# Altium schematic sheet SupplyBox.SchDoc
size C; SheetNumber: 1; SheetTotal: 1
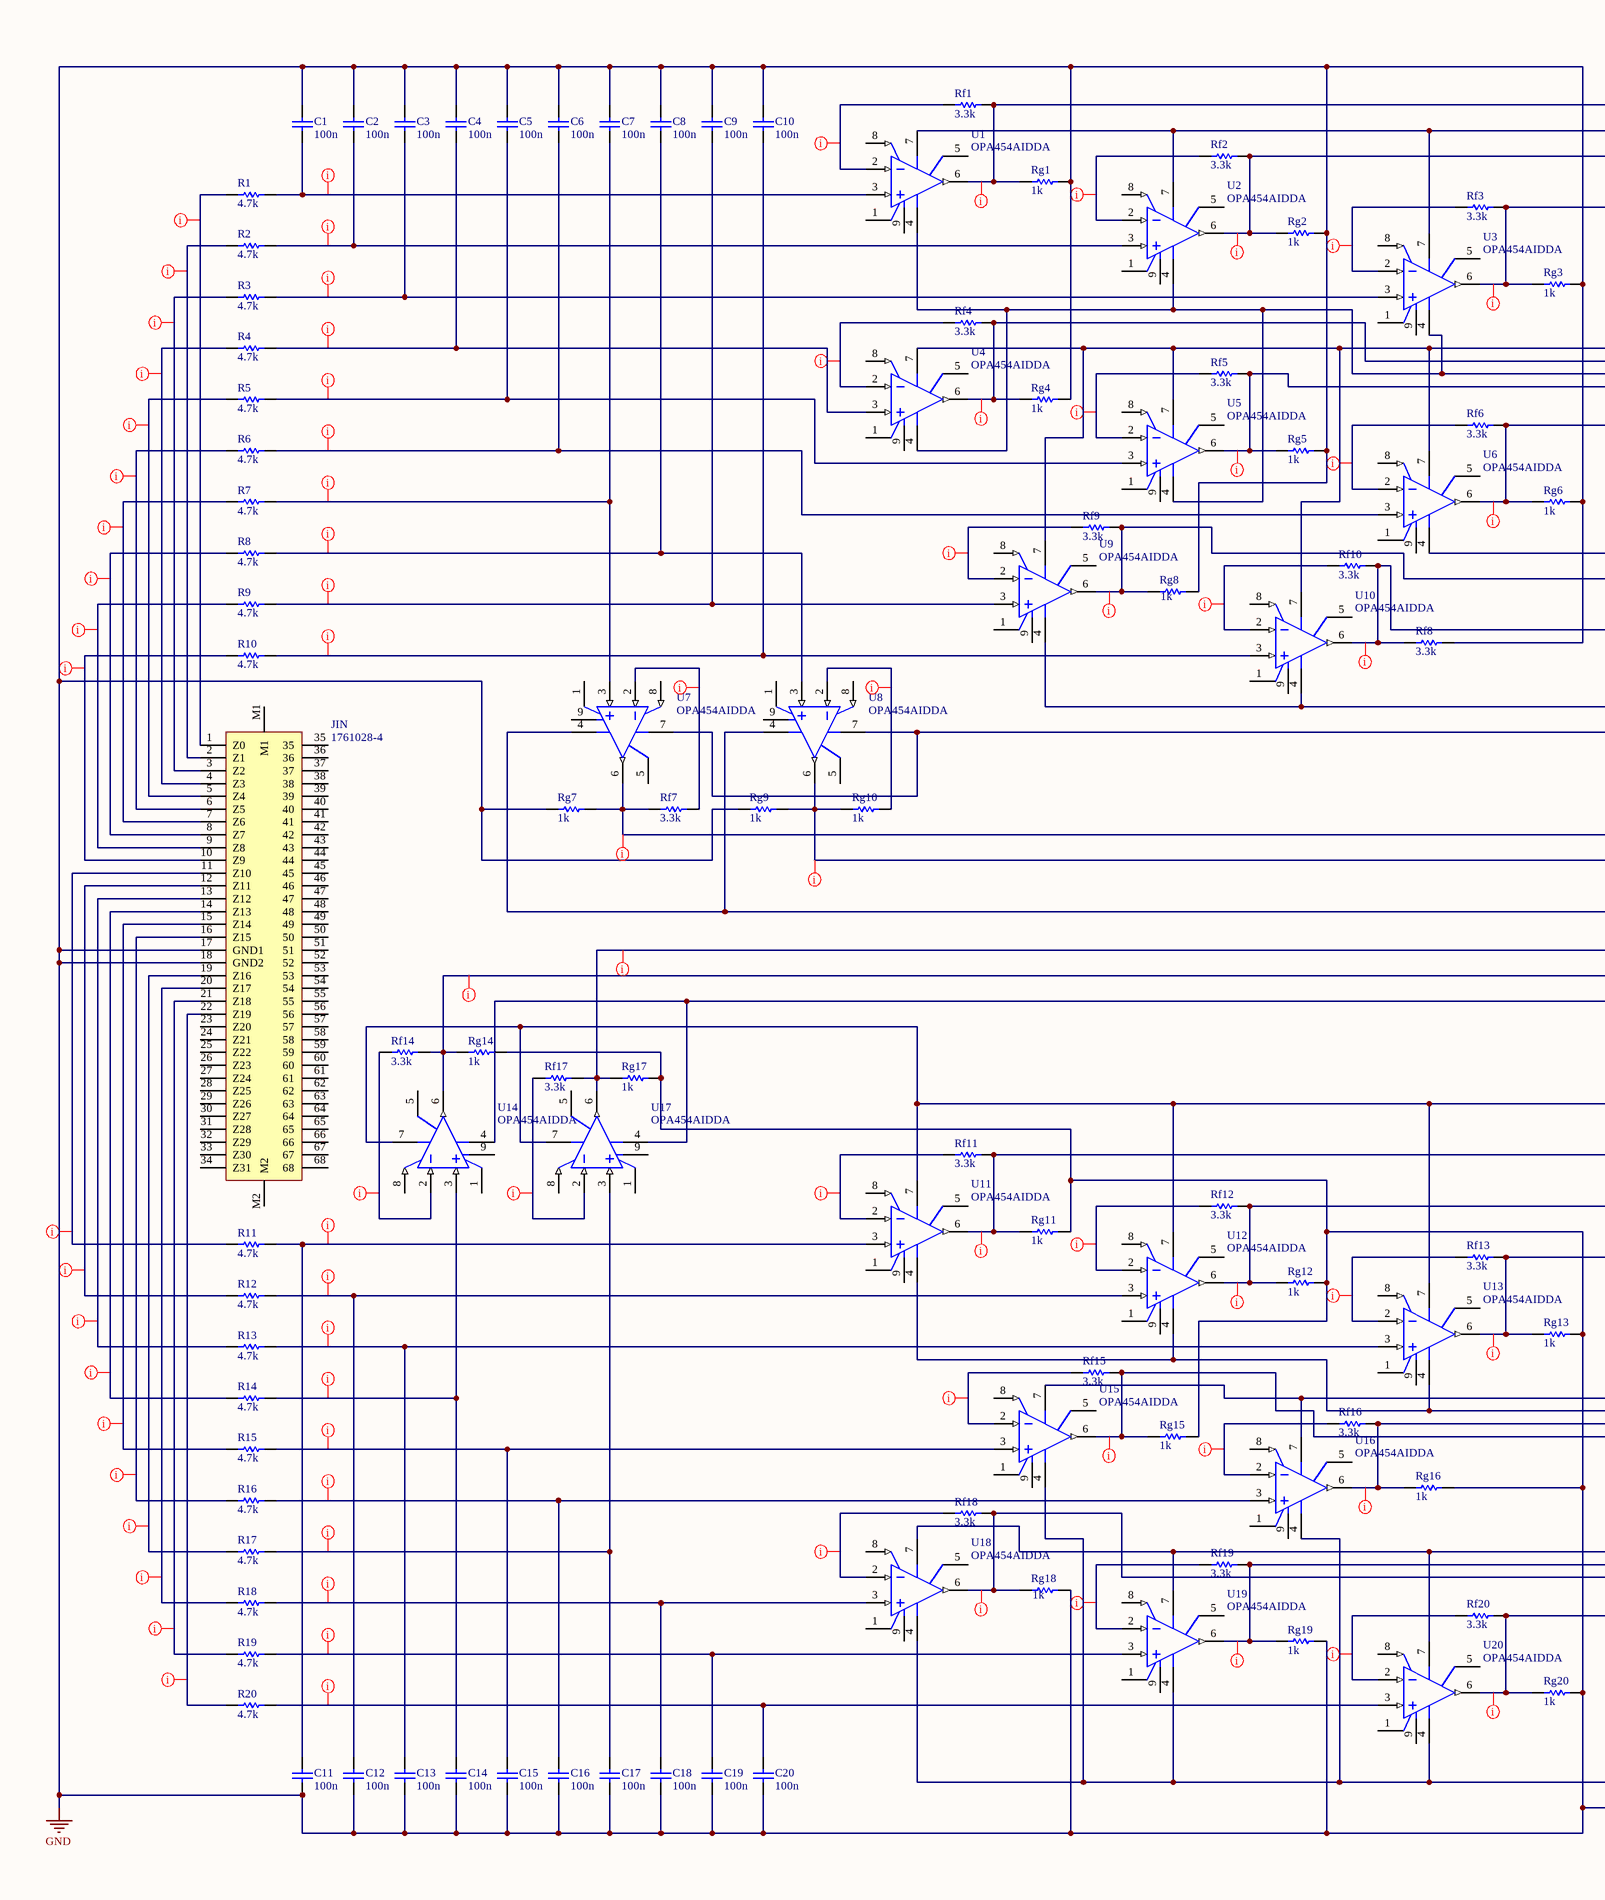
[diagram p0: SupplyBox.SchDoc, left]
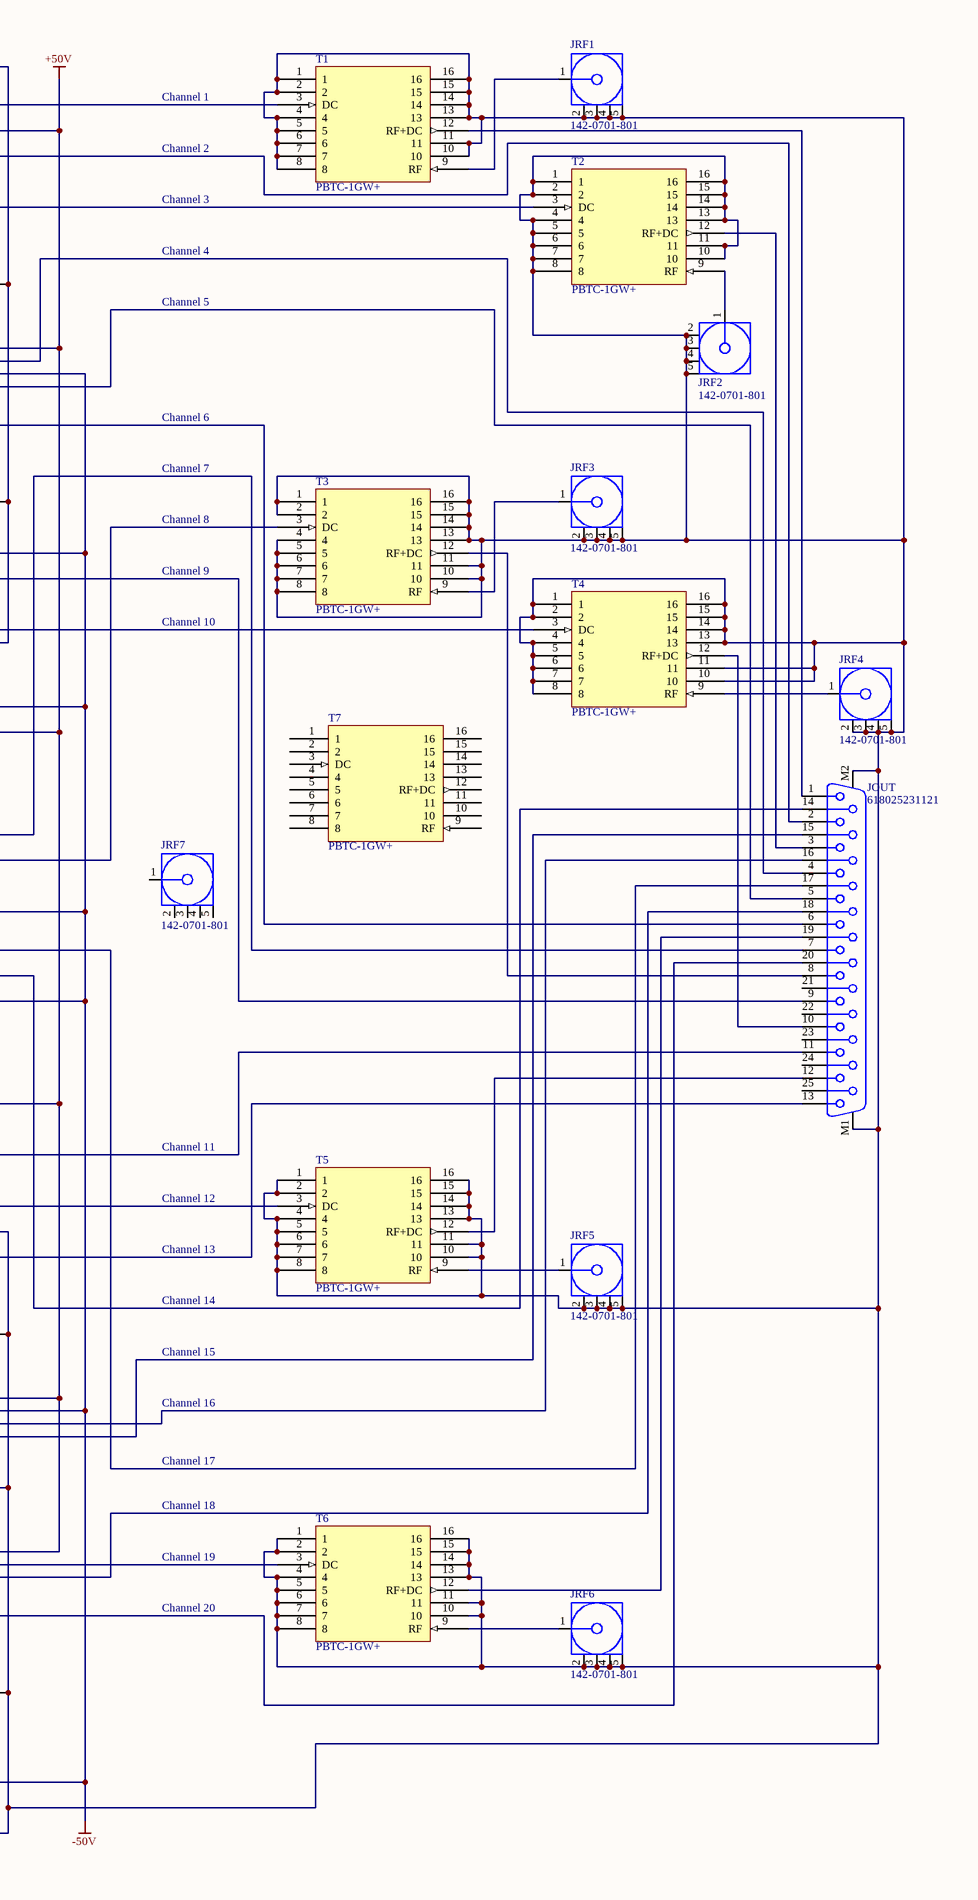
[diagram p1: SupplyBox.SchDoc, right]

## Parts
C1  100n  [CAPC2013X145X48NL20T23]
C2  100n  [CAPC2013X145X48NL20T23]
C3  100n  [CAPC2013X145X48NL20T23]
C4  100n  [CAPC2013X145X48NL20T23]
C5  100n  [CAPC2013X145X48NL20T23]
C6  100n  [CAPC2013X145X48NL20T23]
C7  100n  [CAPC2013X145X48NL20T23]
C8  100n  [CAPC2013X145X48NL20T23]
C9  100n  [CAPC2013X145X48NL20T23]
C10  100n  [CAPC2013X145X48NL20T23]
C11  100n  [CAPC2013X145X48NL20T23]
C12  100n  [CAPC2013X145X48NL20T23]
C13  100n  [CAPC2013X145X48NL20T23]
C14  100n  [CAPC2013X145X48NL20T23]
C15  100n  [CAPC2013X145X48NL20T23]
C16  100n  [CAPC2013X145X48NL20T23]
C17  100n  [CAPC2013X145X48NL20T23]
C18  100n  [CAPC2013X145X48NL20T23]
C19  100n  [CAPC2013X145X48NL20T23]
C20  100n  [CAPC2013X145X48NL20T23]
JIN  1761028-4  [1761028-4-Footprint-1]
JOUT  618025231121  [618025231121]
JRF1  142-0701-801  [CINC-142-0701-801_V]
JRF2  142-0701-801  [CINC-142-0701-801_V]
JRF3  142-0701-801  [CINC-142-0701-801_V]
JRF4  142-0701-801  [CINC-142-0701-801_V]
JRF5  142-0701-801  [CINC-142-0701-801_V]
JRF6  142-0701-801  [CINC-142-0701-801_V]
JRF7  142-0701-801  [CINC-142-0701-801_V]
R1  4.7k  [RESC2013X60X35NL10T20]
R2  4.7k  [RESC2013X60X35NL10T20]
R3  4.7k  [RESC2013X60X35NL10T20]
R4  4.7k  [RESC2013X60X35NL10T20]
R5  4.7k  [RESC2013X60X35NL10T20]
R6  4.7k  [RESC2013X60X35NL10T20]
R7  4.7k  [RESC2013X60X35NL10T20]
R8  4.7k  [RESC2013X60X35NL10T20]
R9  4.7k  [RESC2013X60X35NL10T20]
R10  4.7k  [RESC2013X60X35NL10T20]
R11  4.7k  [RESC2013X60X35NL10T20]
R12  4.7k  [RESC2013X60X35NL10T20]
R13  4.7k  [RESC2013X60X35NL10T20]
R14  4.7k  [RESC2013X60X35NL10T20]
R15  4.7k  [RESC2013X60X35NL10T20]
R16  4.7k  [RESC2013X60X35NL10T20]
R17  4.7k  [RESC2013X60X35NL10T20]
R18  4.7k  [RESC2013X60X35NL10T20]
R19  4.7k  [RESC2013X60X35NL10T20]
R20  4.7k  [RESC2013X60X35NL10T20]
Rf1  3.3k  [RESC2013X60X35ML10T20]
Rf2  3.3k  [RESC2013X60X35ML10T20]
Rf3  3.3k  [RESC2013X60X35ML10T20]
Rf4  3.3k  [RESC2013X60X35ML10T20]
Rf5  3.3k  [RESC2013X60X35ML10T20]
Rf6  3.3k  [RESC2013X60X35ML10T20]
Rf7  3.3k  [RESC2013X60X35ML10T20]
Rf8  3.3k  [RESC2013X60X35ML10T20]
Rf9  3.3k  [RESC2013X60X35ML10T20]
Rf10  3.3k  [RESC2013X60X35ML10T20]
Rf11  3.3k  [RESC2013X60X35ML10T20]
Rf12  3.3k  [RESC2013X60X35ML10T20]
Rf13  3.3k  [RESC2013X60X35ML10T20]
Rf14  3.3k  [RESC2013X60X35ML10T20]
Rf15  3.3k  [RESC2013X60X35ML10T20]
Rf16  3.3k  [RESC2013X60X35ML10T20]
Rf17  3.3k  [RESC2013X60X35ML10T20]
Rf18  3.3k  [RESC2013X60X35ML10T20]
Rf19  3.3k  [RESC2013X60X35ML10T20]
Rf20  3.3k  [RESC2013X60X35ML10T20]
Rg1  1k  [RESC2013X60X35ML10T20]
Rg2  1k  [RESC2013X60X35ML10T20]
Rg3  1k  [RESC2013X60X35ML10T20]
Rg4  1k  [RESC2013X60X35ML10T20]
Rg5  1k  [RESC2013X60X35ML10T20]
Rg6  1k  [RESC2013X60X35ML10T20]
Rg7  1k  [RESC2013X60X35ML10T20]
Rg8  1k  [RESC2013X60X35ML10T20]
Rg9  1k  [RESC2013X60X35ML10T20]
Rg10  1k  [RESC2013X60X35ML10T20]
Rg11  1k  [RESC2013X60X35ML10T20]
Rg12  1k  [RESC2013X60X35ML10T20]
Rg13  1k  [RESC2013X60X35ML10T20]
Rg14  1k  [RESC2013X60X35ML10T20]
Rg15  1k  [RESC2013X60X35ML10T20]
Rg16  1k  [RESC2013X60X35ML10T20]
Rg17  1k  [RESC2013X60X35ML10T20]
Rg18  1k  [RESC2013X60X35ML10T20]
Rg19  1k  [RESC2013X60X35ML10T20]
Rg20  1k  [RESC2013X60X35ML10T20]
T1  PBTC-1GW+  [PBTC-1GW+]
T2  PBTC-1GW+  [PBTC-1GW+]
T3  PBTC-1GW+  [PBTC-1GW+]
T4  PBTC-1GW+  [PBTC-1GW+]
T5  PBTC-1GW+  [PBTC-1GW+]
T6  PBTC-1GW+  [PBTC-1GW+]
T7  PBTC-1GW+  [PBTC-1GW+]
U1  OPA454AIDDA  [DDA0008C_L]
U2  OPA454AIDDA  [DDA0008C_L]
U3  OPA454AIDDA  [DDA0008C_L]
U4  OPA454AIDDA  [DDA0008C_L]
U5  OPA454AIDDA  [DDA0008C_L]
U6  OPA454AIDDA  [DDA0008C_L]
U7  OPA454AIDDA  [DDA0008C_L]
U8  OPA454AIDDA  [DDA0008C_L]
U9  OPA454AIDDA  [DDA0008C_L]
U10  OPA454AIDDA  [DDA0008C_L]
U11  OPA454AIDDA  [DDA0008C_L]
U12  OPA454AIDDA  [DDA0008C_L]
U13  OPA454AIDDA  [DDA0008C_L]
U14  OPA454AIDDA  [DDA0008C_L]
U15  OPA454AIDDA  [DDA0008C_L]
U16  OPA454AIDDA  [DDA0008C_L]
U17  OPA454AIDDA  [DDA0008C_L]
U18  OPA454AIDDA  [DDA0008C_L]
U19  OPA454AIDDA  [DDA0008C_L]
U20  OPA454AIDDA  [DDA0008C_L]

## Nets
+50V: U1.7(V+) U2.7(V+) U3.7(V+) U4.7(V+) U5.7(V+) U6.7(V+) U7.7(V+) U8.7(V+) U9.7(V+) U10.7(V+) U11.7(V+) U12.7(V+) U13.7(V+) U14.7(V+) U15.7(V+) U16.7(V+) U17.7(V+) U18.7(V+) U19.7(V+) U20.7(V+)
-50V: U1.4(V-) U2.4(V-) U3.4(V-) U4.4(V-) U5.4(V-) U6.4(V-) U7.4(V-) U8.4(V-) U9.4(V-) U10.4(V-) U11.4(V-) U12.4(V-) U13.4(V-) U14.4(V-) U15.4(V-) U16.4(V-) U17.4(V-) U18.4(V-) U19.4(V-) U20.4(V-)
GND: C1.2 C2.2 C3.2 C4.2 C5.2 C6.2 C7.2 C8.2 C9.2 C10.2 C11.1 C12.1 C13.1 C14.1 C15.1 C16.1 C17.1 C18.1 C19.1 C20.1 JIN.17(GND1) JIN.18(GND2) JOUT.M1 JOUT.M2 JRF1.2 JRF1.3 JRF1.4 JRF1.5 JRF2.2 JRF2.3 JRF2.4 JRF2.5 JRF3.2 JRF3.3 JRF3.4 JRF3.5 JRF4.2 JRF4.3 JRF4.4 JRF4.5 JRF5.2 JRF5.3 JRF5.4 JRF5.5 JRF6.2 JRF6.3 JRF6.4 JRF6.5 Rf8.2 Rg1.2 Rg2.2 Rg3.2 Rg4.2 Rg5.2 Rg6.2 Rg7.1 Rg8.2 Rg9.1 Rg11.2 Rg12.2 Rg13.2 Rg14.2 Rg15.2 Rg16.2 Rg17.2 Rg18.2 Rg19.2 Rg20.2 T1.1 T1.2 T1.4 T1.5 T1.6 T1.7 T1.8 T1.10 T1.11 T1.13 T1.14 T1.15 T1.16 T2.1 T2.2 T2.4 T2.5 T2.6 T2.7 T2.8 T2.10 T2.11 T2.13 T2.14 T2.15 T2.16 T3.1 T3.2 T3.4 T3.5 T3.6 T3.7 T3.8 T3.10 T3.11 T3.13 T3.14 T3.15 T3.16 T4.1 T4.2 T4.4 T4.5 T4.6 T4.7 T4.8 T4.10 T4.11 T4.13 T4.14 T4.15 T4.16 T5.1 T5.2 T5.4 T5.5 T5.6 T5.7 T5.8 T5.10 T5.11 T5.13 T5.14 T5.15 T5.16 T6.1 T6.2 T6.4 T6.5 T6.6 T6.7 T6.8 T6.10 T6.11 T6.13 T6.14 T6.15 T6.16
NetC1_1: C1.1 R1.2 U1.3(IN+)
NetC2_1: C2.1 R2.2 U2.3(IN+)
NetC3_1: C3.1 R3.2 U3.3(IN+)
NetC4_1: C4.1 R4.2 U4.3(IN+)
NetC5_1: C5.1 R5.2 U5.3(IN+)
NetC6_1: C6.1 R6.2 U6.3(IN+)
NetC7_1: C7.1 R7.2 U7.3(IN+)
NetC8_1: C8.1 R8.2 U8.3(IN+)
NetC9_1: C9.1 R9.2 U9.3(IN+)
NetC10_1: C10.1 R10.2 U10.3(IN+)
NetC11_2: C11.2 R11.2 U11.3(IN+)
NetC12_2: C12.2 R12.2 U12.3(IN+)
NetC13_2: C13.2 R13.2 U13.3(IN+)
NetC14_2: C14.2 R14.2 U14.3(IN+)
NetC15_2: C15.2 R15.2 U15.3(IN+)
NetC16_2: C16.2 R16.2 U16.3(IN+)
NetC17_2: C17.2 R17.2 U17.3(IN+)
NetC18_2: C18.2 R18.2 U18.3(IN+)
NetC19_2: C19.2 R19.2 U19.3(IN+)
NetC20_2: C20.2 R20.2 U20.3(IN+)
NetJIN_1: JIN.1(Z0) R1.1
NetJIN_2: JIN.2(Z1) R2.1
NetJIN_3: JIN.3(Z2) R3.1
NetJIN_4: JIN.4(Z3) R4.1
NetJIN_5: JIN.5(Z4) R5.1
NetJIN_6: JIN.6(Z5) R6.1
NetJIN_7: JIN.7(Z6) R7.1
NetJIN_8: JIN.8(Z7) R8.1
NetJIN_9: JIN.9(Z8) R9.1
NetJIN_10: JIN.10(Z9) R10.1
NetJIN_11: JIN.11(Z10) R11.1
NetJIN_12: JIN.12(Z11) R12.1
NetJIN_13: JIN.13(Z12) R13.1
NetJIN_14: JIN.14(Z13) R14.1
NetJIN_15: JIN.15(Z14) R15.1
NetJIN_16: JIN.16(Z15) R16.1
NetJIN_19: JIN.19(Z16) R17.1
NetJIN_20: JIN.20(Z17) R18.1
NetJIN_21: JIN.21(Z18) R19.1
NetJIN_22: JIN.22(Z19) R20.1
NetJOUT_1: JOUT.1 T1.12(RF+DC)
NetJOUT_2: JOUT.2 Rf2.2 Rg2.1 U2.6(OUT)
NetJOUT_3: JOUT.3 T2.12(RF+DC)
NetJOUT_4: JOUT.4 Rf4.2 Rg4.1 U4.6(OUT)
NetJOUT_5: JOUT.5 Rf5.2 Rg5.1 U5.6(OUT)
NetJOUT_6: JOUT.6 Rf6.2 Rg6.1 U6.6(OUT)
NetJOUT_7: JOUT.7 Rf7.1 Rg7.2 U7.6(OUT)
NetJOUT_8: JOUT.8 T3.12(RF+DC)
NetJOUT_9: JOUT.9 Rf9.2 Rg8.1 U9.6(OUT)
NetJOUT_10: JOUT.10 T4.12(RF+DC)
NetJOUT_11: JOUT.11 Rf11.2 Rg11.1 U11.6(OUT)
NetJOUT_12: JOUT.12 T5.12(RF+DC)
NetJOUT_13: JOUT.13 Rf13.2 Rg13.1 U13.6(OUT)
NetJOUT_14: JOUT.14 Rf14.2 Rg14.1 U14.6(OUT)
NetJOUT_15: JOUT.15 Rf15.2 Rg15.1 U15.6(OUT)
NetJOUT_16: JOUT.16 Rf16.2 Rg16.1 U16.6(OUT)
NetJOUT_17: JOUT.17 Rf17.2 Rg17.1 U17.6(OUT)
NetJOUT_18: JOUT.18 Rf18.2 Rg18.1 U18.6(OUT)
NetJOUT_19: JOUT.19 T6.12(RF+DC)
NetJOUT_20: JOUT.20 Rf20.2 Rg20.1 U20.6(OUT)
NetJRF1_1: JRF1.1 T1.9(RF)
NetJRF2_1: JRF2.1 T2.9(RF)
NetJRF3_1: JRF3.1 T3.9(RF)
NetJRF4_1: JRF4.1 T4.9(RF)
NetJRF5_1: JRF5.1 T5.9(RF)
NetJRF6_1: JRF6.1 T6.9(RF)
NetRf1_1: Rf1.1 U1.2(IN-)
NetRf1_2: Rf1.2 Rg1.1 T1.3(DC) U1.6(OUT)
NetRf2_1: Rf2.1 U2.2(IN-)
NetRf3_1: Rf3.1 U3.2(IN-)
NetRf3_2: Rf3.2 Rg3.1 T2.3(DC) U3.6(OUT)
NetRf4_1: Rf4.1 U4.2(IN-)
NetRf5_1: Rf5.1 U5.2(IN-)
NetRf6_1: Rf6.1 U6.2(IN-)
NetRf7_2: Rf7.2 U7.2(IN-)
NetRf8_1: Rf8.1 Rf10.2 T4.3(DC) U10.6(OUT)
NetRf9_1: Rf9.1 U9.2(IN-)
NetRf10_1: Rf10.1 U10.2(IN-)
NetRf11_1: Rf11.1 U11.2(IN-)
NetRf12_1: Rf12.1 U12.2(IN-)
NetRf12_2: Rf12.2 Rg12.1 T5.3(DC) U12.6(OUT)
NetRf13_1: Rf13.1 U13.2(IN-)
NetRf14_1: Rf14.1 U14.2(IN-)
NetRf15_1: Rf15.1 U15.2(IN-)
NetRf16_1: Rf16.1 U16.2(IN-)
NetRf17_1: Rf17.1 U17.2(IN-)
NetRf18_1: Rf18.1 U18.2(IN-)
NetRf19_1: Rf19.1 U19.2(IN-)
NetRf19_2: Rf19.2 Rg19.1 T6.3(DC) U19.6(OUT)
NetRf20_1: Rf20.1 U20.2(IN-)
NetRg9_2: Rg9.2 Rg10.1 T3.3(DC) U8.6(OUT)
NetRg10_2: Rg10.2 U8.2(IN-)

Not connected (* = marked no-connect by the designer): JIN 23(Z20) 24(Z21) 25(Z22) 26(Z23) 27(Z24) 28(Z25) 29(Z26) 30(Z27) 31(Z28) 32(Z29) 33(Z30) 34(Z31) 35 36 37 38 39 40 41 42 43 44 45 46 47 48 49 50 51 52 53 54 55 56 57 58 59 60 61 62 63 64 65 66 67 68 M1 M2; JOUT 21 22 23 24 25; JRF7 1 2 3 4 5; T7 1 2 3(DC) 4 5 6 7 8 9(RF) 10 11 12(RF+DC) 13 14 15 16; U1 1(E/D_COM) 5(STATUS_FLAG) 8(E/D) 9(EP); U2 1(E/D_COM) 5(STATUS_FLAG) 8(E/D) 9(EP); U3 1(E/D_COM) 5(STATUS_FLAG) 8(E/D) 9(EP); U4 1(E/D_COM) 5(STATUS_FLAG) 8(E/D) 9(EP); U5 1(E/D_COM) 5(STATUS_FLAG) 8(E/D) 9(EP); U6 1(E/D_COM) 5(STATUS_FLAG) 8(E/D) 9(EP); U7 1(E/D_COM) 5(STATUS_FLAG) 8(E/D) 9(EP); U8 1(E/D_COM) 5(STATUS_FLAG) 8(E/D) 9(EP); U9 1(E/D_COM) 5(STATUS_FLAG) 8(E/D) 9(EP); U10 1(E/D_COM) 5(STATUS_FLAG) 8(E/D) 9(EP); U11 1(E/D_COM) 5(STATUS_FLAG) 8(E/D) 9(EP); U12 1(E/D_COM) 5(STATUS_FLAG) 8(E/D) 9(EP); U13 1(E/D_COM) 5(STATUS_FLAG) 8(E/D) 9(EP); U14 1(E/D_COM) 5(STATUS_FLAG) 8(E/D) 9(EP); U15 1(E/D_COM) 5(STATUS_FLAG) 8(E/D) 9(EP); U16 1(E/D_COM) 5(STATUS_FLAG) 8(E/D) 9(EP); U17 1(E/D_COM) 5(STATUS_FLAG) 8(E/D) 9(EP); U18 1(E/D_COM) 5(STATUS_FLAG) 8(E/D) 9(EP); U19 1(E/D_COM) 5(STATUS_FLAG) 8(E/D) 9(EP); U20 1(E/D_COM) 5(STATUS_FLAG) 8(E/D) 9(EP)

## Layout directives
net class Before_Filter: NetJIN_1, NetJIN_2, NetJIN_3, NetJIN_4, NetJIN_5, NetJIN_6, NetJIN_7, NetJIN_8, NetJIN_9, NetJIN_10, NetJIN_11, NetJIN_12, NetJIN_13, NetJIN_14, NetJIN_15, NetJIN_16, NetJIN_19, NetJIN_20, NetJIN_21, NetJIN_22
net class Filter_Amplifier: NetC1_1, NetC2_1, NetC3_1, NetC4_1, NetC5_1, NetC6_1, NetC7_1, NetC8_1, NetC9_1, NetC10_1, NetC11_2, NetC12_2, NetC13_2, NetC14_2, NetC15_2, NetC16_2, NetC17_2, NetC18_2, NetC19_2, NetC20_2
net class Amplifier_feedback: NetRf1_1, NetRf2_1, NetRf3_1, NetRf4_1, NetRf5_1, NetRf6_1, NetRf7_2, NetRf9_1, NetRf10_1, NetRf11_1, NetRf12_1, NetRf13_1, NetRf14_1, NetRf15_1, NetRf16_1, NetRf17_1, NetRf18_1, NetRf19_1, NetRf20_1, NetRg10_2
net class Amplifier_Output: NetJOUT_2, NetJOUT_4, NetJOUT_5, NetJOUT_6, NetJOUT_7, NetJOUT_9, NetJOUT_11, NetJOUT_13, NetJOUT_14, NetJOUT_15, NetJOUT_16, NetJOUT_17, NetJOUT_18, NetJOUT_20, NetRf1_2, NetRf3_2, NetRf8_1, NetRf12_2, NetRf19_2, NetRg9_2

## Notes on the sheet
- Channel 1
- Channel 2
- Channel 3
- Channel 4
- Channel 5
- Channel 6
- Channel 7
- Channel 8
- Channel 9
- Channel 10
- Channel 11
- Channel 12
- Channel 13
- Channel 14
- Channel 15
- Channel 16
- Channel 17
- Channel 18
- Channel 19
- Channel 20

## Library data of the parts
C1-C20 = CMP-2007-03167-1: Manufacturer: Vitramon; Part Number: VJ0805Y104KNAAT
JIN = CMP-002-00071-1: Telecom and Datacom Connector, 68 Contact(s), Female, Right Angle, Solder Terminal, #2-56, Receptacle
JOUT = CMP-1502-00202-2: NexarPartId: 18818207; Pitch: 2.77mm; Operating Supply Voltage: 125V; Gender: Female; Insulation Resistance: 5GΩ; Contact Resistance: 30mΩ; Current Rating: 3A; Number of Contacts: 25
JRF1-JRF7 = CMP-2000-05490-1: SMA End Launch Jack Receptacle, 50 Ohm, 0 to 18 GHz, -65 to 165 degC, 5-Pin SMD, RoHS, Bulk; Manufacturer: EmersonConnectivitySolutions; Connector Type: JackPCB; Gender: Jack(Female); Impedance: 50Ohms; Brand: Johnson/EmersonConnectivitySolutions; Body Material: Brass; Body Style: Straight; Maximum Frequency: 18GHz
R1-R20 = CMP-1659-00011-4: Chip Resistor, 47 KOhm, +/- 1%, 0.125 W, -55 to 155 degC, 0805 (2012 Metric), RoHS, Tape and Reel; Manufacturer: Yageo; Voltage Rating: 150 V
Rf1-Rf20 = CMP-1013-00567-2: Chip Resistor, 3.3 KOhm, +/- 1%, 0.125 W, -55 to 155 degC, 0805 (2012 Metric), RoHS, Tape and Reel; Manufacturer: Yageo; Voltage Rating: 150V; Max Power Dissipation: 125mW; Temperature Coefficient: 100ppm/degreesC
Rg1-Rg20 = CMP-2100-03671-1: Chip Resistor, 1 KOhm, +/- 1%, 125 mW, -55 to 155 degC, 0805 (2012 Metric), RoHS, Tape and Reel; Manufacturer: Yageo; Temperature Coefficient: 100ppm/degreesC; Voltage Rating (DC): 150V; Max Power Dissipation: 125mW; Resistance: 1KOhm
T1-T7 = CMP-00025-00003-1: Monitor TEE DC Block, 0.1MHz Min, 1000MHz Max, 1dB Insertion Loss-Max
U1-U20 = CMP-0017-00714-2: High Voltage (100V), High-Current (50mA) Operational Amplifier, G=1 Stable, 10 to 100 V, -55 to 125 degC, 8-pin SOP (DDA8), Green (RoHS & no Sb/Br); Manufacturer: Texas Instruments; Number of Channels: 1; CMRR(Min)(dB): 100; Rating: Catalog; Total Supply Voltage(Min)(+5V is 5, +/-5V is 10): 10; Offset Drift(Typ)(uV/C): 1.6; Vn at 1kHz(Typ)(nV/rtHz): 47; Slew Rate(Typ)(V/us): 13; Sub Family: General Purpose Amplifier, High Output Current Amplifier (>=50mA), High Supply Voltage Amplifier (>=30V), Precision Amplifier; Iq per channel(Max)(mA): 4; GBW(Typ)(MHz): 2.5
